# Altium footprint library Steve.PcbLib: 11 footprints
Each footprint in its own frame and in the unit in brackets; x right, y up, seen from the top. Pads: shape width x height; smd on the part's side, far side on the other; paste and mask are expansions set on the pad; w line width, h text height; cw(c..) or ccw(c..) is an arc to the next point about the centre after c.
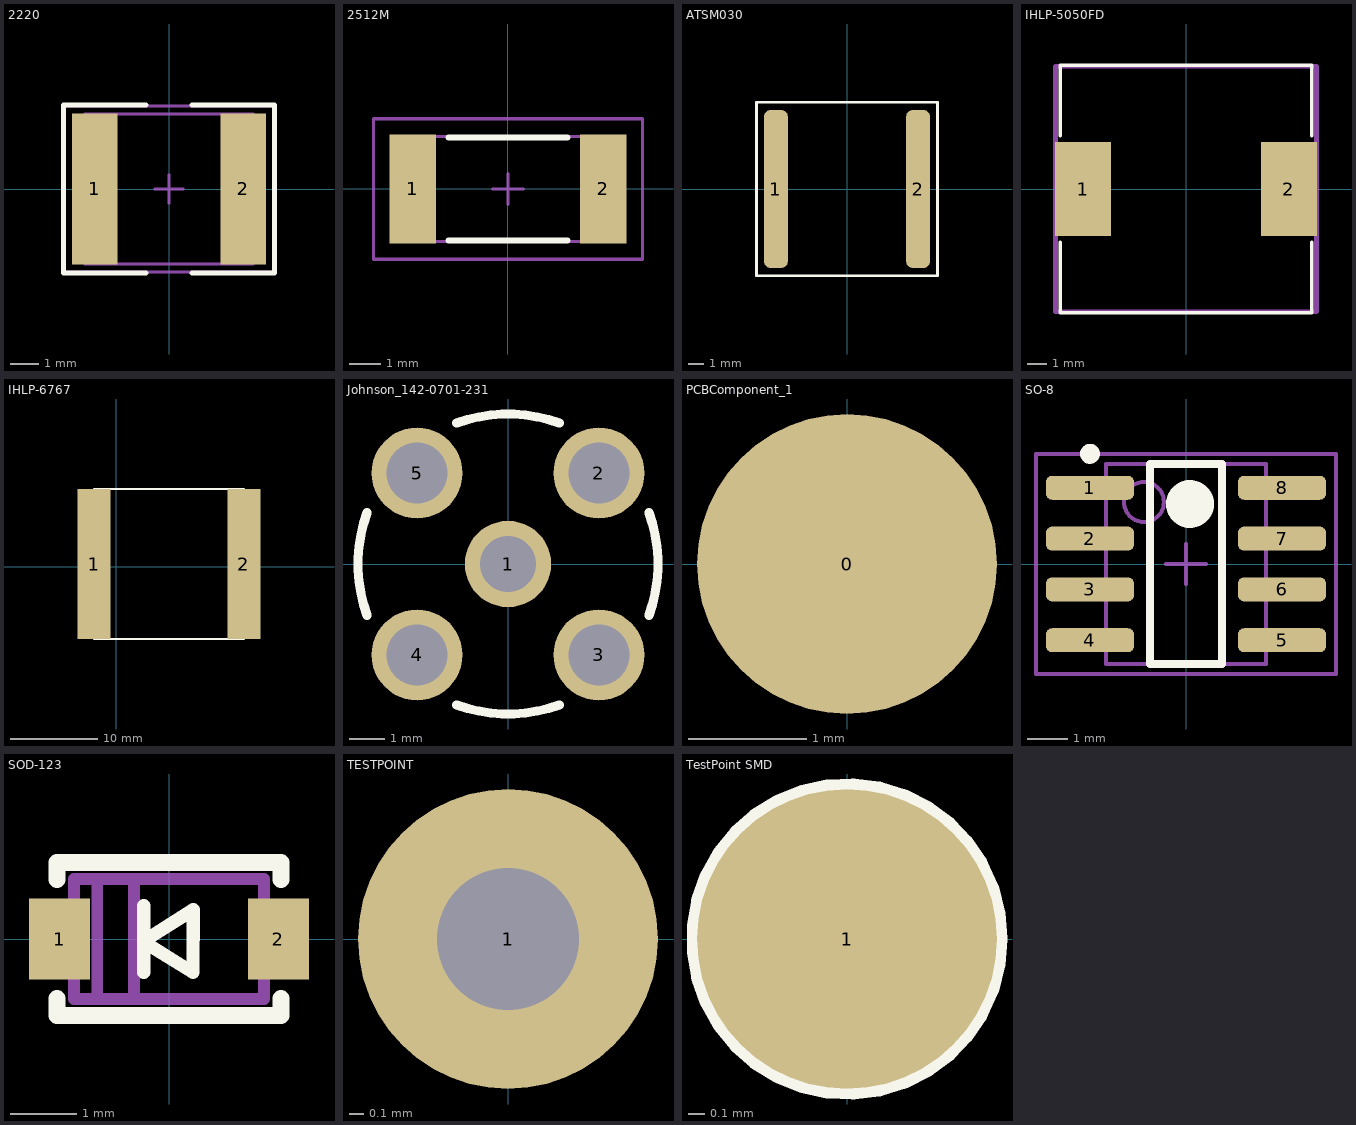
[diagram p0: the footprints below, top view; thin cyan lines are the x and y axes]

## 2220 [mm] "Chip Capacitor, Body 5.7x5.0mm, IPC Medium Density"
height 1.35
pads (2):
  rect 1.6x5.3 smd: 1(-2.6,0) 2(2.6,0)
Top Overlay:
  lines w0.178: -0.811,-2.939 -3.693,-2.939 -3.693,2.939 -0.811,2.939 ; 0.811,-2.939 3.693,-2.939 3.693,2.939 0.811,2.939
Mechanical 5:
  text ".Designator" at -1.524,-0.508 h1.02
Mechanical 13:
  lines w0.1: -2.75,-2.625 -2.75,2.625 ; 2.75,-2.625 2.75,2.625 ; -2.95,-2.625 -2.95,2.625 2.95,2.625 2.95,-2.625 -2.95,-2.625
Mechanical 15:
  lines w0.1: -0.5,0 0.5,0 ; 0,-0.5 0,0.5 ; -3.65,-2.9 -3.65,2.9 3.65,2.9 3.65,-2.9 -3.65,-2.9
3D body: height 1.35, standoff 0, extent -2.949,-2.624 -2.751,2.624
3D body: height 1.35, standoff 0, extent -2.749,-2.624 2.749,2.624
3D body: height 1.35, standoff 0, extent 2.751,-2.624 2.949,2.624

## 2512M [mm] "Chip Resistor, Body 6.3x3.2mm, IPC Low Density"
height 0.71
pads (2):
  rect 1.5x3.5 smd: 1(-3.05,0) 2(3.05,0)
Top Overlay:
  lines w0.2: -1.9,-1.65 1.9,-1.65 ; -1.9,1.65 1.9,1.65
Mechanical 5:
  text ".Designator" at -1.524,-0.508 h1.02
Mechanical 13:
  lines w0.1: -2.463,-1.675 -2.463,1.675 ; 2.463,-1.675 2.463,1.675 ; -3.225,-1.675 -3.225,1.675 3.225,1.675 3.225,-1.675 -3.225,-1.675
Mechanical 15:
  lines w0.1: -0.5,0 0.5,0 ; 0,-0.5 0,0.5 ; -4.3,-2.25 -4.3,2.25 4.3,2.25 4.3,-2.25 -4.3,-2.25
3D body: height 0.71, standoff 0, extent 2.464,-1.674 3.224,1.674
3D body: height 0.71, standoff 0, extent -2.462,-1.674 2.462,1.674
3D body: height 0.71, standoff 0, extent -3.224,-1.674 -2.464,1.674

## ATSM030 [mil] "Gowanda recommended land pattern"
height 360
pads (2):
  rrect50% 60x400 smd: 1(-180,0) 2(180,0)
Top Overlay:
  lines w7: -229,-220 0,-220 229,-220 229,0 229,220 0,220 -229,220 -229,0 -229,-220
Mechanical 5:
  text ".Designator" at -60,-20 h40
3D body: height 359.84, standoff 0, extent -220,-220 220.16,219.59

## IHLP-5050FD [mm] "Vishay Dale recommended land pattern.  Document 34123 rev 18-Sep-09"
height 6.5
pads (2):
  rect 2.945x4.95 smd: 1(-5.407,0) 2(5.407,0)
Top Overlay:
  lines w0.178: -6.6,-2.8 -6.6,-6.5 0,-6.5 6.6,-6.5 6.6,-2.8 ; -6.6,2.8 -6.6,6.5 0,6.5 6.6,6.5 6.6,2.8
Mechanical 5:
  text ".Designator" at -1.524,-0.508 h1.02
Mechanical 13:
  lines w0.254: -6.86,-6.45 0,-6.45 6.86,-6.45 6.86,0 6.86,6.45 0,6.45 -6.86,6.45 -6.86,0 -6.86,-6.45
3D body: height 6.5, standoff 0, extent -6.859,-6.449 6.859,6.449

## IHLP-6767 [mil] "IHLP-6767 Vishay/Dale inductor"
height 53.15
pads (2):
  rect 150x675 smd: 1(-100,12.5) 2(575,12.5)
Top Overlay:
  lines w10: -100,-325 575,-325 575,350 -100,350 -100,-325
Mechanical 5:
  text ".Designator" at 40,30 h40
Mechanical 13:
  lines w3.94: -66.93,-35.43 -66.93,35.43 ; -47.24,-35.43 -47.24,35.43
Mechanical 15:
  lines w3.94: -92.52,-125 -92.52,46.26

## Johnson_142-0701-231 [mil] "Johnson Components recommended land pattern"
height 375
pads (5):
  round 95 hole 62: 1(0,0)
  round 100 hole 67: 2(100,100) 3(100,-100) 4(-100,-100) 5(-100,100)
Top Overlay:
  lines w10: -155.05,-56.43 cw(c0,0) -155.05,56.43 ; -56.43,-155.05 ccw(c0,0) 56.43,-155.05 ; -56.43,155.05 cw(c0,0) 56.43,155.05 ; 155.05,-56.43 ccw(c0,0) 155.05,56.43
Mechanical 5:
  text ".Designator" at 197,-21 h60
3D body: height 375, standoff -110, extent -155.81,-155.95 156.01,155.96

## PCBComponent_1 [mil]
pads (1):
  round 100 all layers, no hole: 0(0,0)

## SO-8 [mm] "SOIC, 8-Leads, Body 5.0x4.0mm (max), Pitch 1.27mm, IPC Medium Density"
height 1.75
pads (8):
  rrect50% 2.2x0.6 smd: 1(-2.4,1.905) 2(-2.4,0.635) 3(-2.4,-0.635) 4(-2.4,-1.905) 5(2.4,-1.905) 6(2.4,-0.635) 7(2.4,0.635) 8(2.4,1.905)
Top Overlay:
  circle w0.6: c0.1,1.5 r0.3
  circle w0.25: c-2.4,2.755 r0.125
  lines w0.2: -0.9,-2.5 0.9,-2.5 0.9,2.5 -0.9,2.5 -0.9,-2.5
Mechanical 5:
  text ".Designator" at -1.524,-0.508 h1.02
Mechanical 13:
  circle w0.1: c-1.05,1.55 r0.5
  lines w0.1: -2,-2.5 2,-2.5 2,2.5 -2,2.5 -2,-2.5
Mechanical 15:
  lines w0.1: -0.5,0 0.5,0 ; 0,-0.5 0,0.5 ; -3.75,-2.75 3.75,-2.75 3.75,2.75 -3.75,2.75 -3.75,-2.75
3D body: height 1.75, standoff 0.1, extent -2,-2.5 2,2.5
3D body: height 1.75, standoff 1.75, extent -1.559,1.041 -0.541,2.059

## SOD-123 [mm] "On Semi recommended land pattern"
height 1.35
pads (2):
  rect 0.915x1.22 smd: 1(-1.637,0) 2(1.637,0)
Top Overlay:
  lines w0.2: -0.381,-0.039 0.359,-0.502 0.362,0.438 -0.381,-0.03
  lines w0.203: -0.381,-0.5 -0.381,0.5
  lines w0.254: -1.676,-0.889 -1.676,-1.143 1.676,-1.143 1.676,-0.889 ; -1.676,0.889 -1.676,1.143 1.676,1.143 1.676,0.889
Mechanical 5:
  text ".Designator" at -1.524,-0.508 h1.02
Mechanical 13:
  lines w0.178: -1.075,-0.902 -1.075,0.902 ; -0.525,-0.902 -0.525,0.902 ; -1.422,-0.902 1.422,-0.902 1.422,0.902 -1.422,0.902 -1.422,-0.902
3D body: height 1.35, standoff 0, extent -1.422,-0.901 1.422,0.901
3D body: height 1.35, standoff 1.35, extent -1.074,-0.901 -0.526,0.901

## TESTPOINT [mil]
height 314.96
pads (1):
  round 80 hole 37.99: 1(0,0)

## TestPoint SMD [mil]
pads (1):
  round 70 smd mask+0: 1(0,0)
Top Overlay:
  circle w5: c0,0 r35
